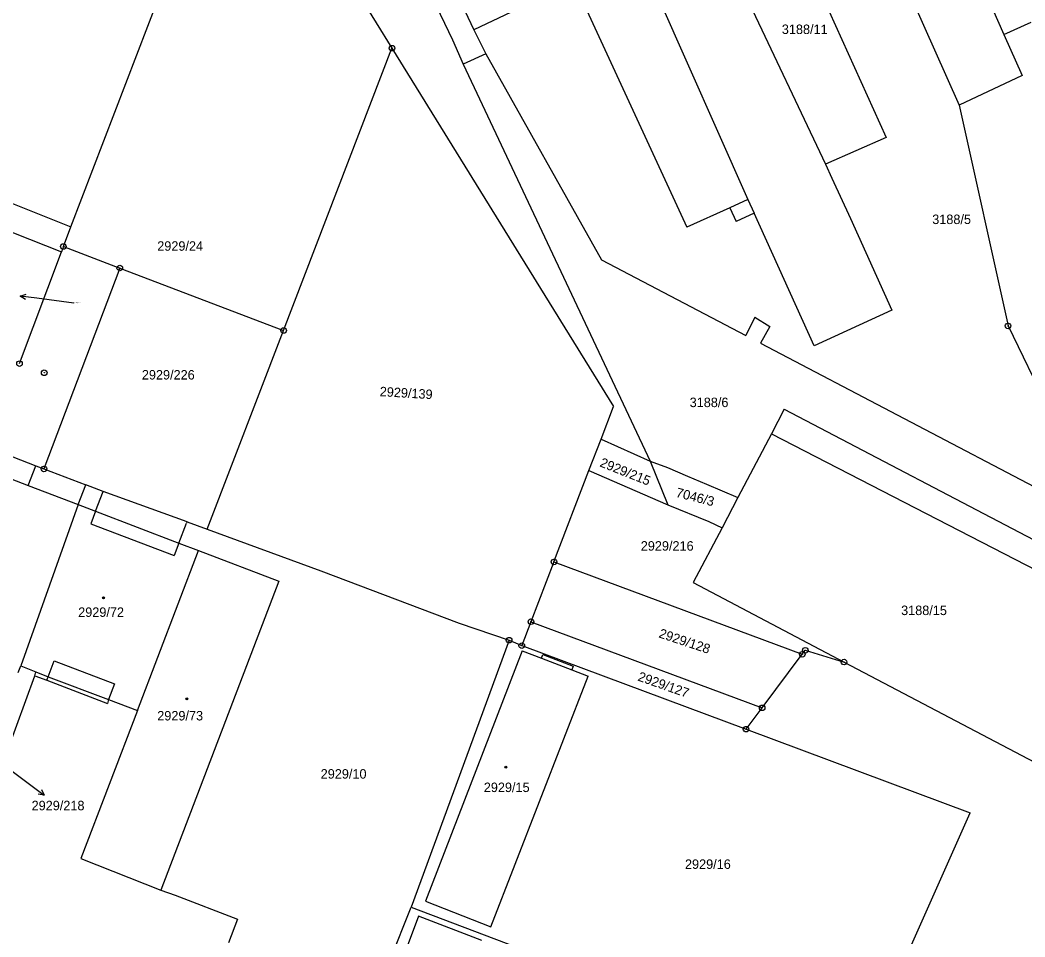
# Model space of a CAD drawing. Extents: x -593183 to -588034, y -1130415 to -1124994.
# Drawn here: x -591984.2 to -591804, y -1128134.3 to -1127969.7 of the extents above; entities that cross this region are included whole.
import ezdxf

# ---------------------------------------------------------------- set-up
doc = ezdxf.new("R2010")
doc.units = 0
for name, color, linetype in [('Vrstva 1', 7, 'Continuous'), ('Vrstva 16', 7, 'Continuous'), ('Vrstva 18', 7, 'Continuous'), ('Vrstva 19', 7, 'Continuous'), ('Vrstva 24', 7, 'Continuous'), ('Vrstva 25', 7, 'Continuous'), ('Vrstva 4', 7, 'Continuous')]:
    doc.layers.add(name, color=color, linetype=linetype)

msp = doc.modelspace()

# ---------------------------------------------------------------- linework, layer by layer
at = {"layer": 'Vrstva 1'}
for p, q in [((-591938.85, -1127895.42), (-591902.87, -1127971.49)), ((-591975.14, -1128006.86), (-591945.54, -1127929.51)), ((-591945.54, -1127929.51), (-591917.55, -1127974.78)), ((-591821.32, -1127932.74), (-591902.87, -1127971.49)), ((-591822.95, -1127938.31), (-591807.8, -1127972.34)), ((-591922.54, -1127939.85), (-591906.72, -1127973.3)), ((-591834.33, -1127943.37), (-591815.84, -1127985.04)), ((-591847.68, -1127949.26), (-591828.95, -1127990.8)), ((-591883.76, -1127965.53), (-591864.69, -1128006.93)), ((-592065.2, -1127970.62), (-591975.14, -1128006.86)), ((-591807.8, -1127972.34), (-591802.91, -1127970.11)), ((-591902.87, -1127971.49), (-591900.7, -1127975.82)), ((-591807.8, -1127972.34), (-591804.52, -1127979.7)), ((-591906.72, -1127973.3), (-591904.8, -1127977.63)), ((-592065.86, -1127976.16), (-591976.84, -1128011.31)), ((-591936.98, -1128025.45), (-591917.55, -1127974.78)), ((-591917.55, -1127974.78), (-591877.79, -1128039.07)), ((-591900.7, -1127975.82), (-591904.8, -1127977.63)), ((-591900.7, -1127975.82), (-591879.99, -1128012.79)), ((-591904.8, -1127977.63), (-591871.27, -1128048.89)), ((-591804.52, -1127979.7), (-591815.84, -1127985.04)), ((-591815.84, -1127985.04), (-591807.07, -1128024.63)), ((-591828.95, -1127990.8), (-591839.78, -1127995.6)), ((-591839.78, -1127995.6), (-591838.67, -1127998.09)), ((-591838.67, -1127998.09), (-591835.31, -1128005.38)), ((-591856.95, -1128003.42), (-591864.69, -1128006.93)), ((-591856.95, -1128003.42), (-591855.83, -1128005.87)), ((-591852.6, -1128004.41), (-591855.83, -1128005.87)), ((-591841.83, -1128028.2), (-591852.6, -1128004.41)), ((-591976.48, -1128010.38), (-591975.14, -1128006.86)), ((-591835.31, -1128005.38), (-591827.88, -1128021.83)), ((-591976.48, -1128010.38), (-591976.84, -1128011.31)), ((-591976.48, -1128010.38), (-591966.36, -1128014.24)), ((-591984.34, -1128031.39), (-591976.84, -1128011.31)), ((-591879.99, -1128012.79), (-591854.1, -1128026.37)), ((-591966.36, -1128014.24), (-591979.95, -1128050.29)), ((-591966.36, -1128014.24), (-591936.98, -1128025.45)), ((-591852.45, -1128023.08), (-591854.1, -1128026.37)), ((-591852.45, -1128023.08), (-591849.76, -1128024.73)), ((-591827.88, -1128021.83), (-591841.83, -1128028.2)), ((-591849.76, -1128024.73), (-591851.43, -1128027.73)), ((-591807.07, -1128024.63), (-591797.09, -1128045.26)), ((-591950.67, -1128061.13), (-591936.98, -1128025.45)), ((-591851.43, -1128027.73), (-591793.19, -1128058.29)), ((-591880.05, -1128044.95), (-591877.79, -1128039.07)), ((-591847.19, -1128039.55), (-591849.51, -1128043.97)), ((-591847.19, -1128039.55), (-591797.14, -1128065.81)), ((-591849.51, -1128043.97), (-591855.51, -1128055.4)), ((-591849.51, -1128043.97), (-591778.1, -1128080.85)), ((-591990.05, -1128046.39), (-591981.44, -1128049.72)), ((-591882.22, -1128050.6), (-591880.05, -1128044.95)), ((-591880.05, -1128044.95), (-591871.27, -1128048.89)), ((-591982.79, -1128053.27), (-591981.44, -1128049.72)), ((-591981.44, -1128049.72), (-591979.95, -1128050.29)), ((-591871.27, -1128048.89), (-591868.14, -1128050.01)), ((-591871.27, -1128048.89), (-591868.07, -1128056.75)), ((-591868.14, -1128050.01), (-591864.53, -1128051.6)), ((-591988.21, -1128051.2), (-591982.79, -1128053.27)), ((-591979.95, -1128050.29), (-591972.47, -1128053.14)), ((-591888.5, -1128066.98), (-591882.22, -1128050.6)), ((-591882.22, -1128050.6), (-591868.07, -1128056.75)), ((-591864.53, -1128051.6), (-591861.14, -1128053.03)), ((-591973.82, -1128056.69), (-591972.47, -1128053.14)), ((-591969.34, -1128054.34), (-591972.47, -1128053.14)), ((-591861.14, -1128053.03), (-591855.51, -1128055.4)), ((-591954.3, -1128059.8), (-591969.34, -1128054.34)), ((-591855.51, -1128055.4), (-591858.36, -1128060.87)), ((-591973.82, -1128056.69), (-591984.13, -1128085.63)), ((-591868.07, -1128056.75), (-591860.74, -1128059.71)), ((-591955.74, -1128063.59), (-591954.39, -1128060.04)), ((-591954.3, -1128059.8), (-591954.39, -1128060.04)), ((-591954.3, -1128059.8), (-591950.67, -1128061.13)), ((-591858.36, -1128060.87), (-591863.53, -1128070.7)), ((-591860.74, -1128059.71), (-591858.36, -1128060.87)), ((-591950.67, -1128061.13), (-591930.28, -1128068.61)), ((-591955.74, -1128063.59), (-591952.24, -1128064.93)), ((-591963.21, -1128093.67), (-591952.24, -1128064.93)), ((-591952.24, -1128064.93), (-591937.85, -1128070.42)), ((-591888.5, -1128066.98), (-591892.62, -1128077.72)), ((-591888.5, -1128066.98), (-591843.96, -1128083.55)), ((-591930.28, -1128068.61), (-591905.48, -1128077.95)), ((-591937.85, -1128070.42), (-591958.98, -1128125.89)), ((-591863.53, -1128070.7), (-591836.48, -1128084.95)), ((-591905.48, -1128077.95), (-591896.54, -1128081.03)), ((-591892.62, -1128077.72), (-591894.27, -1128082.01)), ((-591892.62, -1128077.72), (-591851.16, -1128093.16)), ((-591896.54, -1128081.03), (-591914.12, -1128128.91)), ((-591896.54, -1128081.03), (-591894.27, -1128082.01)), ((-591894.27, -1128082.01), (-591854.04, -1128097)), ((-591894.21, -1128082.93), (-591911.53, -1128127.86)), ((-591894.21, -1128082.93), (-591890.76, -1128084.26)), ((-591890.76, -1128084.26), (-591890.51, -1128083.61)), ((-591890.51, -1128083.61), (-591885.05, -1128085.71)), ((-591851.16, -1128093.16), (-591843.96, -1128083.55)), ((-591843.96, -1128083.55), (-591843.43, -1128082.83)), ((-591843.43, -1128082.83), (-591836.48, -1128084.95)), ((-591984.13, -1128085.63), (-591981.43, -1128086.7)), ((-591885.05, -1128085.71), (-591885.3, -1128086.37)), ((-591836.48, -1128084.95), (-591792.3, -1128108.21)), ((-591986.45, -1128100.72), (-591981.61, -1128087.4)), ((-591981.61, -1128087.4), (-591981.43, -1128086.7)), ((-591981.61, -1128087.4), (-591979.46, -1128088.23)), ((-591899.83, -1128132.48), (-591882.36, -1128087.5)), ((-591885.3, -1128086.37), (-591882.36, -1128087.5)), ((-591979.46, -1128088.23), (-591968.58, -1128092.41)), ((-591968.36, -1128091.7), (-591968.58, -1128092.41)), ((-591968.36, -1128091.7), (-591963.21, -1128093.67)), ((-591854.04, -1128097), (-591851.16, -1128093.16)), ((-591963.21, -1128093.67), (-591973.33, -1128120.19)), ((-591854.04, -1128097), (-591813.84, -1128112.01)), ((-591832.07, -1128152.96), (-591813.84, -1128112.01)), ((-591973.33, -1128120.19), (-591958.98, -1128125.89)), ((-591958.98, -1128125.89), (-591956.41, -1128126.76)), ((-591956.41, -1128126.76), (-591945.27, -1128131.08)), ((-591920.83, -1128145.83), (-591914.12, -1128128.91)), ((-591914.12, -1128128.91), (-591889.67, -1128138.18)), ((-591911.53, -1128127.86), (-591899.83, -1128132.48)), ((-591945.27, -1128131.08), (-591946.85, -1128135.33)), ((-591912.81, -1128130.57), (-591923.82, -1128160.3)), ((-591901.41, -1128134.92), (-591912.81, -1128130.57))]:
    msp.add_line(p, q, dxfattribs=at)
at = {"layer": 'Vrstva 16'}
for p, q in [((-591974.6, -1128020.57), (-591981.24, -1128019.67)), ((-591988.74, -1128102.22), (-591982.3, -1128107.04))]:
    msp.add_line(p, q, dxfattribs=at)
at = {"layer": 'Vrstva 24'}
for centre, radius in [((-591917.55, -1127974.78), 0.5), ((-591917.55, -1127974.78), 0.0327), ((-591976.48, -1128010.38), 0.5), ((-591976.48, -1128010.38), 0.0327), ((-591966.36, -1128014.24), 0.5), ((-591966.36, -1128014.24), 0.0327), ((-591936.98, -1128025.45), 0.5), ((-591807.07, -1128024.63), 0.5), ((-591807.07, -1128024.63), 0.0327), ((-591936.98, -1128025.45), 0.0327), ((-591984.34, -1128031.39), 0.5), ((-591979.91, -1128033.04), 0.5), ((-591979.91, -1128033.04), 0.0327), ((-591979.95, -1128050.29), 0.5), ((-591979.95, -1128050.29), 0.0327), ((-591888.5, -1128066.98), 0.5), ((-591888.5, -1128066.98), 0.0327), ((-591892.62, -1128077.72), 0.5), ((-591892.62, -1128077.72), 0.0327), ((-591896.54, -1128081.03), 0.5), ((-591896.54, -1128081.03), 0.0327), ((-591894.27, -1128082.01), 0.5), ((-591894.27, -1128082.01), 0.0327), ((-591843.43, -1128082.83), 0.5), ((-591843.96, -1128083.55), 0.5), ((-591843.96, -1128083.55), 0.0327), ((-591843.43, -1128082.83), 0.0327), ((-591836.48, -1128084.95), 0.5), ((-591836.48, -1128084.95), 0.0327), ((-591851.16, -1128093.16), 0.5), ((-591851.16, -1128093.16), 0.0327), ((-591854.04, -1128097), 0.5), ((-591854.04, -1128097), 0.0327)]:
    msp.add_circle(centre, radius, dxfattribs=at)
at = {"layer": 'Vrstva 25'}
for p, q in [((-591981.24, -1128019.67), (-591984.21, -1128019.27)), ((-591982.3, -1128107.04), (-591979.9, -1128108.84))]:
    msp.add_line(p, q, dxfattribs=at)
for points in [[(-591983.29, -1128019.9), (-591984.21, -1128019.27), (-591983.16, -1128018.91)], [(-591980.4, -1128107.84), (-591979.9, -1128108.84), (-591981, -1128108.64)]]:
    msp.add_lwpolyline(points, dxfattribs=at)
for centre, radius in [((-591969.26, -1128073.43), 0.175), ((-591969.26, -1128073.43), 0.15), ((-591954.35, -1128091.55), 0.175), ((-591954.35, -1128091.55), 0.15), ((-591897.13, -1128103.79), 0.175), ((-591897.13, -1128103.79), 0.15)]:
    msp.add_circle(centre, radius, dxfattribs=at)
at = {"layer": 'Vrstva 4'}
for p, q in [((-591859.3, -1127954.5), (-591839.78, -1127995.6)), ((-591872.19, -1127960.31), (-591853.71, -1128001.95)), ((-591853.71, -1128001.95), (-591856.95, -1128003.42)), ((-591853.71, -1128001.95), (-591852.6, -1128004.41)), ((-591982.79, -1128053.27), (-591973.82, -1128056.69)), ((-591970.69, -1128057.89), (-591969.34, -1128054.34)), ((-591973.82, -1128056.69), (-591970.69, -1128057.89)), ((-591970.69, -1128057.89), (-591971.55, -1128060.13)), ((-591970.69, -1128057.89), (-591955.74, -1128063.59)), ((-591971.55, -1128060.13), (-591956.6, -1128065.84)), ((-591955.74, -1128063.59), (-591956.6, -1128065.84)), ((-591890.76, -1128084.26), (-591885.3, -1128086.37)), ((-591984.57, -1128086.83), (-591984.13, -1128085.63)), ((-591979.21, -1128087.58), (-591978.13, -1128084.73)), ((-591978.13, -1128084.73), (-591967.28, -1128088.85)), ((-591981.43, -1128086.7), (-591979.21, -1128087.58)), ((-591979.46, -1128088.23), (-591979.21, -1128087.58)), ((-591979.21, -1128087.58), (-591968.36, -1128091.7)), ((-591967.28, -1128088.85), (-591968.36, -1128091.7))]:
    msp.add_line(p, q, dxfattribs=at)

# ---------------------------------------------------------------- texts
at = {"layer": 'Vrstva 16'}
msp.add_text('2929/218', height=1.7, dxfattribs=at).set_placement((-591982.17, -1128111.55))
at = {"layer": 'Vrstva 18'}
for s, height, p in [('3188/5', 1.7, (-591820.66, -1128006.35)), ('2929/24', 1.7, (-591959.64, -1128011.14)), ('2929/225', 0.2, (-591974.6, -1128020.57)), ('2929/226', 1.7, (-591962.4, -1128034.25)), ('3188/6', 1.7, (-591864.16, -1128039.2)), ('2929/216', 1.7, (-591872.93, -1128064.96)), ('3188/15', 1.7, (-591826.24, -1128076.52)), ('2929/10', 1.7, (-591930.33, -1128105.87)), ('2929/16', 1.7, (-591865, -1128122.07))]:
    msp.add_text(s, height=height, dxfattribs=at).set_placement(p)
for s, rotation, p in [('2929/139', 356.6336, (-591919.78, -1128037.23)), ('2929/215', 338.1802, (-591880.41, -1128049.8)), ('7046/3', 345.532, (-591866.74, -1128055.28)), ('2929/128', 341.6011, (-591869.82, -1128080.5)), ('2929/127', 340.5914, (-591873.59, -1128088.24))]:
    msp.add_text(s, height=1.7, rotation=rotation, dxfattribs=at).set_placement(p)
at = {"layer": 'Vrstva 19'}
for s, p in [('3188/11', (-591847.63, -1127972.25)), ('2929/72', (-591973.82, -1128076.85)), ('2929/73', (-591959.64, -1128095.43)), ('2929/15', (-591901.08, -1128108.28))]:
    msp.add_text(s, height=1.7, dxfattribs=at).set_placement(p)

doc.saveas('drawing.dxf')
